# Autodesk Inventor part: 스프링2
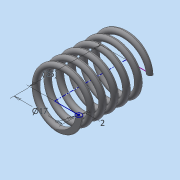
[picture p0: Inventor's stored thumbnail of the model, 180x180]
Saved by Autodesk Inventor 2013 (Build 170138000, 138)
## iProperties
Created: 2019-07
Part Number: 스프링2
Material: 강철, 탄소
Document SubType Name: Modeling
Designer: dgall
Density: 7.87 g/cm^3
Mass: 0.980803 g
Surface Area: 19.9894 cm^2
Volume: 0.980803 cm^3
Author: dgall
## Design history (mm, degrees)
sketch "스케치1"
  geometry: L1 (8.5, 0)-(0, 0); L2 (0, 0)-(0, 16); L3 (0, 16)-(8.5, 16); C1 r 1 at (8.5, 0)
  constraints: 6 end point, 2 parallel, 1 centre point, 1 coincident, 1 horizontal, 1 perpendicular
  dimensions: "d0" = 17 diameter of L1.start L2; "d2" = 16 distance of L1.end L2.end (derived); "d3" = 2 diameter of C1
feature "코일1" pitch "d4" = 10; turns "d6" = 6; dims "d5" = 16 (= d2), "d7" = 0, angle "d8" = 90 deg, angle "d9" = 90 deg, "d10" = 0, "d11" = 0
node "작업 평면1"
feature "분할1"
feature "분할2"
node "솔리드1"
